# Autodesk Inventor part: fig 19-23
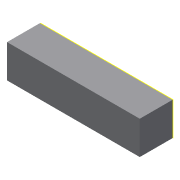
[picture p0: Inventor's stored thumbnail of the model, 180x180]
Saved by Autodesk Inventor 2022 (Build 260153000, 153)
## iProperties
Created: 2013-07
Part Number: fig 19-23
Material: Generic
Document SubType Name: Modeling
Designer: CADCIM
Density: 1 g/cm^3
Appearance: Default
Author: CADCIM
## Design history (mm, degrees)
sketch "Sketch1"
  geometry: L1 (-20, 5)-(20, 5); L2 (20, 5)-(20, -5); L3 (20, -5)-(-20, -5); L4 (-20, -5)-(-20, 5); L5 (-20, 5)-(20, -5); L6 (20, 5)-(-20, -5); 1 further point
  constraints: 12 end point, 2 midpoint, 2 parallel, 1 horizontal, 1 perpendicular
  dimensions: "d0" = 40 distance of L2.end L3.end; "d1" = 10 distance of L1.end L2.end
extrude "Extrusion1" new body sketch "Sketch1" distance "d2" = 10; taper "d3" = 0 deg
sketch "Sketch2"
  geometry: L1 (0, 0)-(40, 0) reference; L2 (0, 0)-(0, -10) reference; L3 (40, -10)-(0, -10) reference; L4 (40, 0)-(40, -10) reference; 2 further points
body "Solid1"
